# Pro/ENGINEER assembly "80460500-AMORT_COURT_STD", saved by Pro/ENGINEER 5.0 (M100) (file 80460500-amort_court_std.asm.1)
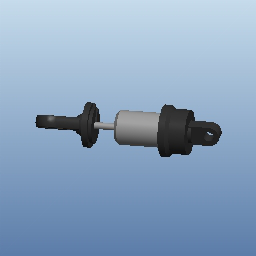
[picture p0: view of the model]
Units: millimeter Newton Second (mmNs); MM, TONNE, HOURS

Other parameters: TRANSLATION1_STATIC_FRICTION, TRANSLATION1_STATIC_FRICTION, TRANSLATION1_KINETIC_FRICTION, TRANSLATION1_KINETIC_FRICTION, TRANSLATION1_RESTITUTION, TRANSLATION1_RESTITUTION, TRANSLATION1_MINIMUM_LIMIT, TRANSLATION1_MINIMUM_LIMIT, TRANSLATION1_MAXIMUM_LIMIT, TRANSLATION1_MAXIMUM_LIMIT, TRANSLATION1_ZERO_POSITION, TRANSLATION1_ZERO_POSITION

Other components: 80460500-C-AMORT_COURT_ST-75073, 80160500-TIGE_AMORT_STD_0-75116

Other named items: A-DROITE, A-DESSUS, A-FACE, A-R0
